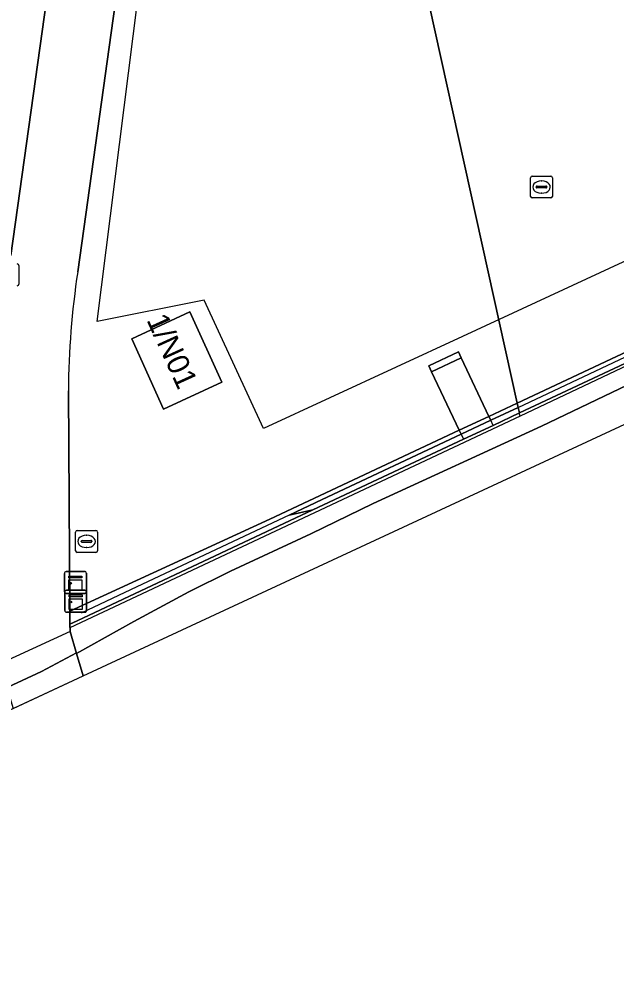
# Model space of a CAD drawing. Extents: x 160806 to 161707, y 383696 to 384148.
# Drawn here: x 161283.31 to 161310.65, y 383741.15 to 383784.33 of the extents above; entities that cross this region are included whole.
import ezdxf

# ---------------------------------------------------------------- set-up
doc = ezdxf.new("R2010")
doc.units = 0
for name, color, linetype in [('IMGEO_Dek', 7, 'Continuous'), ('IMGEO_Fietspad_open', 7, 'Continuous'), ('IMGEO_Groenvoorziening', 7, 'Continuous'), ('IMGEO_Hek', 7, 'Continuous'), ('IMGEO_Kast', 7, 'Continuous'), ('IMGEO_Kolk', 7, 'Continuous'), ('IMGEO_Muur', 7, 'Continuous'), ('IMGEO_Pand', 7, 'Continuous'), ('IMGEO_Pand_nummerreeks', 7, 'Continuous'), ('IMGEO_Pand_vergunning_verleend', 7, 'Continuous'), ('IMGEO_Rioolput', 7, 'Continuous'), ('IMGEO_Spoorbaan_halfverhard', 7, 'Continuous'), ('IMGEO_Spoorbaan_open', 7, 'Continuous'), ('IMGEO_Terreindeel_gesloten', 7, 'Continuous'), ('IMGEO_Voetgangersgebied_open', 7, 'Continuous'), ('IMGEO_Voetpad_op_trap', 7, 'Continuous'), ('IMGEO_Voetpad_open', 7, 'Continuous')]:
    doc.layers.add(name, color=color, linetype=linetype)

msp = doc.modelspace()

# ---------------------------------------------------------------- linework, layer by layer
at = {"layer": 'IMGEO_Dek'}
msp.add_lwpolyline([(161302.206, 383768.201), (161303.47, 383765.52), (161303.556, 383765.337), (161303.663, 383765.111), (161305.021, 383765.747), (161304.913, 383765.977), (161304.828, 383766.158), (161303.562, 383768.841), (161303.434, 383769.112), (161302.078, 383768.472)], close=True, dxfattribs=at)
at = {"layer": 'IMGEO_Fietspad_open'}
msp.add_lwpolyline([(161282.95, 383773.511), (161288.794, 383815.268), (161288.857, 383815.733), (161291.768, 383837.353), (161291.85, 383837.936), (161287.024, 383840.083), (161286.521, 383836.429), (161285.845, 383831.524), (161285.72, 383830.612), (161285.573, 383829.546), (161280.045, 383789.307), (161279.962, 383788.923)], dxfattribs=at)
at = {"layer": 'IMGEO_Groenvoorziening'}
for points in [[(161285.58, 383767.33), (161285.649, 383757.252), (161294.794, 383761.449), (161303.47, 383765.52), (161304.828, 383766.158), (161306.126, 383766.767), (161298.089, 383803.089), (161297.905, 383804.094), (161297.497, 383806.322), (161292.113, 383814.612), (161291.849, 383814.638), (161286.008, 383772.772)], [(161353.142, 383788.84), (161345.557, 383785.277), (161344.962, 383784.997), (161344.422, 383784.744), (161331.617, 383778.728), (161306.126, 383766.767), (161306.17, 383766.569), (161306.227, 383766.312), (161344.529, 383784.251), (161345.081, 383784.51), (161345.678, 383784.79), (161353.357, 383788.389)]]:
    msp.add_lwpolyline(points, dxfattribs=at)
for points in [[(161291.132, 383770.935), (161292.601, 383767.718), (161289.931, 383766.49), (161288.478, 383769.707)], [(161302.078, 383768.472), (161303.434, 383769.112), (161303.562, 383768.841), (161302.206, 383768.201)], [(161304.828, 383766.158), (161303.47, 383765.52), (161294.794, 383761.449), (161285.649, 383757.252), (161285.653, 383756.655), (161285.978, 383756.8), (161296.767, 383761.881), (161295.69, 383761.645), (161297.189, 383762.349), (161303.556, 383765.337), (161304.913, 383765.977), (161306.17, 383766.569), (161306.126, 383766.767)]]:
    msp.add_lwpolyline(points, close=True, dxfattribs=at)
msp.add_arc((161323.898, 383767.054), 38.319, 171.4186, 179.5876, dxfattribs=at)
at = {"layer": 'IMGEO_Hek'}
for points in [[(161304.913, 383765.977), (161306.17, 383766.569), (161314.338, 383770.42), (161324.98, 383775.393), (161337.778, 383781.392), (161350.576, 383787.419), (161357.031, 383790.441), (161365.479, 383794.338), (161372.031, 383797.151), (161378.634, 383799.703), (161383.104, 383801.204), (161385.56, 383801.947)], [(161303.556, 383765.337), (161303.47, 383765.52), (161302.206, 383768.201), (161302.078, 383768.472), (161303.434, 383769.112), (161303.562, 383768.841), (161304.828, 383766.158), (161304.913, 383765.977)], [(161303.556, 383765.337), (161297.189, 383762.349), (161295.69, 383761.645), (161288.711, 383758.369), (161286.158, 383757.158)]]:
    msp.add_lwpolyline(points, dxfattribs=at)
at = {"layer": 'IMGEO_Kast'}
for p, q in [((161285.402, 383758.137), (161285.402, 383758.978)), ((161285.402, 383758.978), (161285.402, 383758.137)), ((161285.477, 383759.062), (161286.318, 383759.062)), ((161286.318, 383759.062), (161285.477, 383759.062)), ((161286.402, 383758.987), (161286.402, 383758.146)), ((161286.402, 383758.146), (161286.402, 383758.987)), ((161285.417, 383757.277), (161285.417, 383758.118)), ((161285.417, 383758.118), (161285.417, 383757.277)), ((161286.327, 383758.062), (161285.486, 383758.062)), ((161285.486, 383758.062), (161286.327, 383758.062)), ((161285.492, 383758.202), (161286.333, 383758.202)), ((161286.333, 383758.202), (161285.492, 383758.202)), ((161286.417, 383758.127), (161286.417, 383757.286)), ((161286.417, 383757.286), (161286.417, 383758.127)), ((161286.342, 383757.202), (161285.501, 383757.202)), ((161285.501, 383757.202), (161286.342, 383757.202))]:
    msp.add_line(p, q, dxfattribs=at)
for points in [[(161285.597, 383758.852), (161286.197, 383758.852), (161286.197, 383758.767), (161285.597, 383758.767), (161285.597, 383758.852)], [(161285.597, 383758.677), (161286.197, 383758.677), (161286.197, 383758.188), (161285.597, 383758.188), (161285.597, 383758.677)], [(161285.612, 383757.992), (161286.212, 383757.992), (161286.212, 383757.907), (161285.612, 383757.907), (161285.612, 383757.992)], [(161285.612, 383757.817), (161286.212, 383757.817), (161286.212, 383757.328), (161285.612, 383757.328), (161285.612, 383757.817)]]:
    msp.add_lwpolyline(points, dxfattribs=at)
for centre in [(161285.681, 383758.526), (161285.696, 383757.666)]:
    msp.add_circle(centre, 0.0377, dxfattribs=at)
for centre, start, end in [((161285.48, 383758.984), 92.4484, 184.2845), ((161285.48, 383758.984), 92.4484, 184.2845), ((161286.324, 383758.984), 2.4484, 94.2845), ((161286.324, 383758.984), 2.4484, 94.2845), ((161285.48, 383758.14), 182.4484, 274.2845), ((161285.48, 383758.14), 182.4484, 274.2845), ((161285.495, 383758.124), 92.4484, 184.2845), ((161285.495, 383758.124), 92.4484, 184.2845), ((161286.324, 383758.14), 272.4484, 4.2845), ((161286.324, 383758.14), 272.4484, 4.2845), ((161286.339, 383758.124), 2.4484, 94.2845), ((161286.339, 383758.124), 2.4484, 94.2845), ((161285.495, 383757.28), 182.4484, 274.2845), ((161285.495, 383757.28), 182.4484, 274.2845), ((161286.339, 383757.28), 272.4484, 4.2845), ((161286.339, 383757.28), 272.4484, 4.2845)]:
    msp.add_arc(centre, 0.0779, start, end, dxfattribs=at)
at = {"layer": 'IMGEO_Kolk'}
for p, q in [((161306.733, 383776.218), (161306.733, 383777.07)), ((161306.808, 383777.144), (161307.66, 383777.144)), ((161307.221, 383776.924), (161307.246, 383776.924)), ((161307.734, 383777.07), (161307.734, 383776.218)), ((161306.992, 383776.638), (161306.992, 383776.65)), ((161307.43, 383776.601), (161307.032, 383776.601)), ((161307.035, 383776.687), (161307.433, 383776.687)), ((161307.476, 383776.65), (161307.476, 383776.638)), ((161307.66, 383776.144), (161306.808, 383776.144)), ((161307.244, 383776.364), (161307.219, 383776.364)), ((161283.314, 383773.055), (161283.314, 383772.203))]:
    msp.add_line(p, q, dxfattribs=at)
for points in [[(161306.733, 383776.218), (161306.733, 383777.07)], [(161306.808, 383777.144), (161307.66, 383777.144)], [(161307.734, 383777.07), (161307.734, 383776.218)], [(161307.66, 383776.144), (161306.808, 383776.144)], [(161283.314, 383773.055), (161283.314, 383772.203)]]:
    msp.add_lwpolyline(points, dxfattribs=at)
for centre, radius, start, end in [((161306.81, 383777.068), 0.0765, 91.552, 178.448), ((161306.81, 383777.068), 0.0765, 91.552, 178.448), ((161307.658, 383777.068), 0.0765, 1.552, 88.448), ((161307.658, 383777.068), 0.0765, 1.552, 88.448), ((161307.032, 383776.647), 0.0403, 85.8775, 175.7526), ((161307.029, 383776.637), 0.0366, 178.938, 274.7102), ((161307.433, 383776.644), 0.043, 264.8664, 352.4533), ((161307.437, 383776.649), 0.0386, 1.7309, 96.639), ((161306.81, 383776.22), 0.0765, 181.552, 268.448), ((161306.81, 383776.22), 0.0765, 181.552, 268.448), ((161307.658, 383776.22), 0.0765, 271.552, 358.448), ((161307.658, 383776.22), 0.0765, 271.552, 358.448), ((161283.238, 383773.053), 0.0765, 1.552, 88.448), ((161283.238, 383773.053), 0.0765, 1.552, 88.448), ((161283.238, 383772.205), 0.0765, 271.552, 358.448), ((161283.238, 383772.205), 0.0765, 271.552, 358.448)]:
    msp.add_arc(centre, radius, start, end, dxfattribs=at)
for centre, major_axis, ratio, start_param, end_param in [((161307.22, 383776.644), (-0.387, 0.002), 0.722429, 4.712389, 7.853982), ((161307.245, 383776.644), (-0.39, 0.002), 0.717154, 1.570796, 4.712389)]:
    msp.add_ellipse(centre, major_axis=major_axis, ratio=ratio, start_param=start_param, end_param=end_param, dxfattribs=at)
at = {"layer": 'IMGEO_Muur'}
for points in [[(161285.653, 383756.655), (161285.978, 383756.8), (161296.767, 383761.881), (161303.663, 383765.111), (161305.021, 383765.747), (161306.227, 383766.312), (161344.529, 383784.251), (161345.081, 383784.51), (161345.678, 383784.79)], [(161336.721, 383780.594), (161306.249, 383766.164)], [(161306.249, 383766.164), (161285.654, 383756.492)], [(161306.249, 383766.164), (161306.217, 383766.307)]]:
    msp.add_lwpolyline(points, dxfattribs=at)
msp.add_lwpolyline([(161295.69, 383761.645), (161296.767, 383761.881), (161303.663, 383765.111), (161305.021, 383765.747), (161306.227, 383766.312), (161306.17, 383766.569), (161304.913, 383765.977), (161303.556, 383765.337), (161297.189, 383762.349)], close=True, dxfattribs=at)
at = {"layer": 'IMGEO_Pand'}
msp.add_lwpolyline([(161291.132, 383770.935), (161288.478, 383769.707), (161289.931, 383766.49), (161292.601, 383767.718)], close=True, dxfattribs=at)
at = {"layer": 'IMGEO_Pand_vergunning_verleend'}
msp.add_lwpolyline([(161286.905, 383770.489), (161291.413, 383806.28), (161303.76, 383808.96), (161303.031, 383812.451), (161323.52, 383816.728), (161325.87, 383813.583), (161332.156, 383815.078), (161338.096, 383790.101), (161336.982, 383788.652), (161333.878, 383784.616), (161329.619, 383781.849), (161303.612, 383769.813), (161294.509, 383765.6), (161291.793, 383771.467)], close=True, dxfattribs=at)
at = {"layer": 'IMGEO_Rioolput'}
for p, q in [((161285.912, 383760.013), (161285.912, 383760.865)), ((161285.987, 383760.939), (161286.839, 383760.939)), ((161286.913, 383760.865), (161286.913, 383760.013)), ((161286.171, 383760.433), (161286.171, 383760.445)), ((161286.214, 383760.482), (161286.612, 383760.482)), ((161286.4, 383760.719), (161286.425, 383760.719)), ((161286.655, 383760.445), (161286.655, 383760.433)), ((161286.609, 383760.396), (161286.211, 383760.396)), ((161286.423, 383760.159), (161286.398, 383760.159)), ((161286.839, 383759.939), (161285.987, 383759.939))]:
    msp.add_line(p, q, dxfattribs=at)
for points in [[(161285.912, 383760.013), (161285.912, 383760.865)], [(161285.987, 383760.939), (161286.839, 383760.939)], [(161286.913, 383760.865), (161286.913, 383760.013)], [(161286.839, 383759.939), (161285.987, 383759.939)]]:
    msp.add_lwpolyline(points, dxfattribs=at)
for centre, radius, start, end in [((161285.989, 383760.863), 0.0765, 91.552, 178.448), ((161285.989, 383760.863), 0.0765, 91.552, 178.448), ((161286.837, 383760.863), 0.0765, 1.552, 88.448), ((161286.837, 383760.863), 0.0765, 1.552, 88.448), ((161286.211, 383760.442), 0.0403, 85.8775, 175.7526), ((161286.208, 383760.432), 0.0366, 178.938, 274.7102), ((161286.612, 383760.439), 0.043, 264.8664, 352.4533), ((161286.616, 383760.444), 0.0386, 1.7309, 96.639), ((161285.989, 383760.015), 0.0765, 181.552, 268.448), ((161285.989, 383760.015), 0.0765, 181.552, 268.448), ((161286.837, 383760.015), 0.0765, 271.552, 358.448), ((161286.837, 383760.015), 0.0765, 271.552, 358.448)]:
    msp.add_arc(centre, radius, start, end, dxfattribs=at)
for centre, major_axis, ratio, start_param, end_param in [((161286.399, 383760.439), (-0.387, 0.002), 0.722429, 4.712389, 7.853982), ((161286.424, 383760.439), (-0.39, 0.002), 0.717154, 1.570796, 4.712389)]:
    msp.add_ellipse(centre, major_axis=major_axis, ratio=ratio, start_param=start_param, end_param=end_param, dxfattribs=at)
at = {"layer": 'IMGEO_Spoorbaan_halfverhard'}
msp.add_lwpolyline([(161348.742, 383785.497), (161341.727, 383782.043), (161334.24, 383778.465), (161328.287, 383775.698), (161321.541, 383772.521), (161318.31, 383770.995), (161313.322, 383768.622), (161307.226, 383765.703), (161299.525, 383762.169), (161296.669, 383760.786), (161293.001, 383759.082), (161291.091, 383758.136), (161288.575, 383756.779), (161285.955, 383755.31), (161286.26, 383754.291), (161375.471, 383795.729)], dxfattribs=at)
at = {"layer": 'IMGEO_Spoorbaan_open'}
msp.add_lwpolyline([(161286.26, 383754.291), (161285.947, 383755.338), (161284.345, 383754.49), (161268.558, 383747.163), (161262.971, 383744.495), (161259.937, 383743.21), (161257.671, 383742.18), (161257.977, 383741.153), (161274.589, 383748.87)], close=True, dxfattribs=at)
at = {"layer": 'IMGEO_Terreindeel_gesloten'}
msp.add_lwpolyline([(161345.081, 383784.51), (161344.529, 383784.251), (161306.227, 383766.312), (161305.021, 383765.747), (161303.663, 383765.111), (161296.767, 383761.881), (161285.978, 383756.8), (161285.653, 383756.655), (161285.655, 383756.314), (161285.955, 383755.31), (161288.575, 383756.779), (161291.091, 383758.136), (161293.001, 383759.082), (161296.669, 383760.786), (161299.525, 383762.169), (161307.226, 383765.703), (161313.322, 383768.622), (161318.31, 383770.995), (161321.541, 383772.521), (161328.287, 383775.698), (161334.24, 383778.465), (161341.727, 383782.043), (161348.742, 383785.497)], dxfattribs=at)
for points in [[(161302.206, 383768.201), (161303.562, 383768.841), (161303.434, 383769.112), (161302.078, 383768.472)], [(161284.345, 383754.49), (161285.947, 383755.338), (161285.655, 383756.314), (161257.339, 383743.293), (161257.671, 383742.18), (161259.937, 383743.21), (161262.971, 383744.495), (161268.558, 383747.163)]]:
    msp.add_lwpolyline(points, close=True, dxfattribs=at)
at = {"layer": 'IMGEO_Voetgangersgebied_open'}
msp.add_lwpolyline([(161292.124, 383839.633), (161291.997, 383838.792), (161291.85, 383837.936), (161291.768, 383837.353), (161288.857, 383815.733), (161291.849, 383814.638), (161292.113, 383814.612), (161308.889, 383813.313), (161320.703, 383816.056), (161322.275, 383809.402), (161297.905, 383804.094), (161298.089, 383803.089), (161306.126, 383766.767), (161331.617, 383778.728), (161344.422, 383784.744), (161344.962, 383784.997), (161345.557, 383785.277), (161342.045, 383799.414), (161341.604, 383801.189), (161336.384, 383800.01)], dxfattribs=at)
at = {"layer": 'IMGEO_Voetpad_op_trap'}
msp.add_lwpolyline([(161302.206, 383768.201), (161303.47, 383765.52), (161303.556, 383765.337), (161303.663, 383765.111), (161305.021, 383765.747), (161304.913, 383765.977), (161304.828, 383766.158), (161303.562, 383768.841), (161303.434, 383769.112), (161302.078, 383768.472)], close=True, dxfattribs=at)
at = {"layer": 'IMGEO_Voetpad_open'}
for points in [[(161286.008, 383772.772), (161291.849, 383814.638), (161288.857, 383815.733), (161288.794, 383815.268), (161282.95, 383773.511)], [(161282.453, 383768.528), (161282.607, 383755.867), (161282.614, 383755.304), (161282.627, 383754.217), (161283.047, 383752.799), (161286.26, 383754.291)], [(161286.26, 383754.291), (161285.955, 383755.31), (161285.655, 383756.314), (161285.653, 383756.655), (161285.649, 383757.252), (161285.58, 383767.33)]]:
    msp.add_lwpolyline(points, dxfattribs=at)
msp.add_arc((161323.898, 383767.054), 38.319, 171.4186, 179.5876, dxfattribs=at)

# ---------------------------------------------------------------- texts
at = {"layer": 'IMGEO_Pand_nummerreeks'}
msp.add_text('1/N01', height=1, rotation=294.425, dxfattribs=at).set_placement((161289.143, 383770.57))

doc.saveas('drawing.dxf')
